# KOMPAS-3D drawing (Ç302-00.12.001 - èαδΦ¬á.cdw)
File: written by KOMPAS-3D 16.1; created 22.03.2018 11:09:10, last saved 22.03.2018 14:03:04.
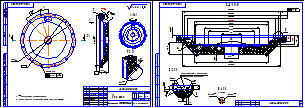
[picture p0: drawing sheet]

Sheets 1-2: A3, landscape

Title block, sheet 1: name: Крышка; designation: А302-00.12.001; material: Полипропилен  ГОСТ 26996-86; mass: 1,43; scale: 1:2; sheet number: 1; sheets: 2; organisation: ЗАО «Астерион»; sheet format: A3; stored path: Z:\Мембранные насосы\Мембранный электропривод\А302-00.00.000 - ASTRA-302 (МЭ200)\Чертежи\А302-00.12.001 - Крышка.cdw; drawn by: Милов; technical control: Лучихин
Title block, sheet 2: sheet number: 2

Views: Вид 1, Вид:4, Проекционный вид 2, Местный разрез 1, Разрез А-А, Выносной элемент 4, Выносной элемент 5, Вид по стрелке 6, Выносной элемент 7, Выносной элемент Б, Выносной элемент, Выносной элемент В, Выносной элемент Г, Вид:1, Вид:2, Вид:3
Referenced files in Z:\Мембранные насосы\Мембранный электропривод\А302-00.00.000 - ASTRA-302 (МЭ200)\3Д\: А302-00.12.001 - Крышка.m3d
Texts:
  Зона контакта с мембраной
  поверхность глянцевая
  ** Обеспечить инструментом.
  Общие допуски ГОСТ 30893.2-mK (H14, h14,  t2/2).
  Ra 3,2
  Ra 3,2 ( )
Dimensions and other numbers on the sheet: 302; 287; 12 отв.; 6,5; 39; 280; 25,5; 51,5; 205; 270±0,4; 32,5; 17; 24,5; 244±0,2; 206; 202; 152; 128; 54; 31; 6; 0,5; 1; 258±0,3; 0,1; 2; 2,5; 12; 2 места; 35; 1:2; 1,43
